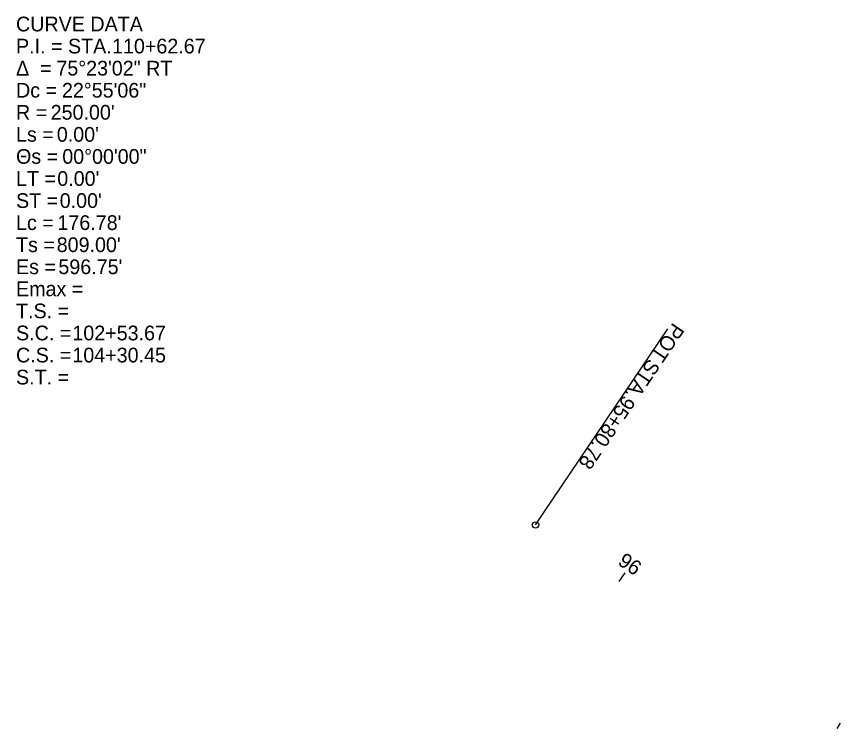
# Model space of a CAD drawing. Extents: x 1600023 to 1602131, y 285824 to 287284.
# Drawn here: x 1600258.1 to 1600414.9, y 287148.6 to 287284.1 of the extents above; entities that cross this region are included whole.
import ezdxf

# ---------------------------------------------------------------- set-up
doc = ezdxf.new("R2010")
doc.units = 0
for name, color, linetype in [('GE_P_Alignment_100_Cardinal_Points', 7, 'Continuous'), ('GE_P_Alignment_100_Curve_Data', 7, 'Continuous'), ('GE_P_Alignment_100_Stations', 7, 'Continuous')]:
    doc.layers.add(name, color=color, linetype=linetype)

msp = doc.modelspace()

# ---------------------------------------------------------------- linework, layer by layer
at = {"layer": 'GE_P_Alignment_100_Cardinal_Points'}
msp.add_line((1600356.88, 287187.32), (1600382.06, 287224.61), dxfattribs=at)
msp.add_circle((1600356.88, 287187.32), 0.6, dxfattribs=at)
at = {"layer": 'GE_P_Alignment_100_Stations'}
for p, q in [((1600372.8, 287176.56), (1600373.92, 287178.22)), ((1600414.24, 287148.57), (1600414.91, 287149.57))]:
    msp.add_line(p, q, dxfattribs=at)

# ---------------------------------------------------------------- texts
at = {"layer": 'GE_P_Alignment_100_Cardinal_Points'}
for s, p in [('POT', (1600383.03, 287225.97)), (' STA. ', (1600379, 287220)), ('95+80.78', (1600373.71, 287212.17))]:
    msp.add_text(s, height=2.8, rotation=235.9623, dxfattribs=at).set_placement(p)
at = {"layer": 'GE_P_Alignment_100_Curve_Data'}
for s, p in [('CURVE DATA', (1600258.03, 287281.25)), ('P.I. = STA. ', (1600258.03, 287277.05)), ('110+62.67', (1600276.3, 287277.05)), ('Δ  = ', (1600258.03, 287272.85)), ('75°23\'02" RT', (1600265.71, 287272.85)), ('Dc = ', (1600258.03, 287268.65)), ('22°55\'06"', (1600266.77, 287268.65)), ('R = ', (1600258.03, 287264.45)), ("250.00'", (1600264.62, 287264.45)), ('Ls = ', (1600258.03, 287260.25)), ("0.00'", (1600265.79, 287260.25)), ('Θs = ', (1600258.03, 287256.05)), ('00°00\'00"', (1600266.83, 287256.05)), ('LT = ', (1600258.03, 287251.85)), ("0.00'", (1600265.88, 287251.85)), ('ST = ', (1600258.03, 287247.65)), ("0.00'", (1600266.34, 287247.65)), ('Lc = ', (1600258.03, 287243.45)), ("176.78'", (1600265.91, 287243.45)), ('Ts = ', (1600258.03, 287239.25)), ("809.00'", (1600265.77, 287239.25)), ('Es = ', (1600258.03, 287235.05)), ("596.75'", (1600266.09, 287235.05)), ('Emax = ', (1600258.03, 287230.85)), ('T.S. = ', (1600258.03, 287226.65)), ('S.C. = ', (1600258.03, 287222.45)), ('102+53.67', (1600268.75, 287222.45)), ('C.S. = ', (1600258.03, 287218.25)), ('104+30.45', (1600268.75, 287218.25)), ('S.T. = ', (1600258.03, 287214.05))]:
    msp.add_text(s, height=2.8, dxfattribs=at).set_placement(p)
at = {"layer": 'GE_P_Alignment_100_Stations'}
msp.add_text('96', height=2.8, rotation=325.9623, dxfattribs=at).set_placement((1600372.35, 287179.89))

doc.saveas('drawing.dxf')
